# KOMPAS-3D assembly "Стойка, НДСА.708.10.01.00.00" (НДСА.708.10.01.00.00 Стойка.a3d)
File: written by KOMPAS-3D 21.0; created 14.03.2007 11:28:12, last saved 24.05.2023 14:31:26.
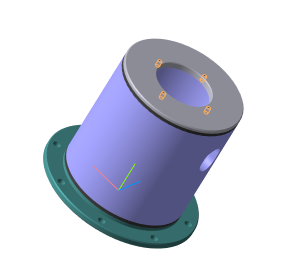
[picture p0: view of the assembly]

Document properties: Полное имя файла: C:\Users\s.pischagina\Desktop\PLM\НДСА.708.10.01.00.00 Стойка.a3d; Автор: Ширяева О.А.; Организация: Эсто-вакуум

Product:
- Part/product: Стойка  | designation НДСА.708.10.01.00.00
    Масса: 10.550806
    additional columns: <item xmlns="http://appius.ru/pdm" xmlns:xs="http://www.w3.org/2001/XMLSchema" x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; <item xmlns="http://appius.ru/pdm" xmlns:xs="http://www.w3.org/2001/XMLSchema" x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; <item xmlns="http://appius.ru/pdm" xmlns:xs="http://www.w3.org/2001/XMLSchema" x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
  - Component [detail]: Шов сварной 1 (стойка)  | qty 2  | Материал: Сталь 20  ГОСТ 1050-88 (density 7820 kg/m3); Масса: 0.054253; additional columns: <item xmlns="http://appius.ru/pdm" xmlns:xs="http://www.w3.org/2001/XMLSchema" x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; <item xmlns="http://appius.ru/pdm" xmlns:xs="http://www.w3.org/2001/XMLSchema" x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; source file: Шов сварной 1 (стойка).m3d
  - Component [detail]: Фланец верхний  | designation НДСА.014.01.09.01.03  | pos. 3  | Материал: Сталь 20  ГОСТ 1050-88 (density 7820 kg/m3); Масса: 1.270585; Форматы листов документа: A4; additional columns: <item xmlns="http://appius.ru/pdm" xmlns:xs="http://www.w3.org/2001/XMLSchema" x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; <item xmlns="http://appius.ru/pdm" xmlns:xs="http://www.w3.org/2001/XMLSchema" x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; <item xmlns="http://appius.ru/pdm" xmlns:xs="http://www.w3.org/2001/XMLSchema" x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; <item xmlns="http://appius.ru/pdm" xmlns:xs="http://www.w3.org/2001/XMLSchema" x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; <item xmlns="http://appius.ru/pdm" xmlns:xs="http://www.w3.org/2001/XMLSchema" x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; <item xmlns="http://appius.ru/pdm" xmlns:xs="http://www.w3.org/2001/XMLSchema" x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; source file: НДСА.014.01.09.01.03 Фланец верхний.CDW, НДСА.014.01.09.01.03 Фланец верхний.m3d
  - Component [detail]: Труба  | designation НДСА.708.10.01.00.01  | pos. 1  | Материал: Труба$d180х10 ГОСТ 8732-78;20 ГОСТ 8731-74$ (density 7859 kg/m3); Масса: 7.249004; additional columns: <item xmlns="http://appius.ru/pdm" xmlns:xs="http://www.w3.org/2001/XMLSchema" x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; <item xmlns="http://appius.ru/pdm" xmlns:xs="http://www.w3.org/2001/XMLSchema" x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; <item xmlns="http://appius.ru/pdm" xmlns:xs="http://www.w3.org/2001/XMLSchema" x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; source file: НДСА.708.10.01.00.01 Труба.CDW, НДСА.708.10.01.00.01 Труба.m3d
  - Component [detail]: Фланец нижний  | designation НДСА.014.01.09.01.01  | pos. 2  | Материал: Сталь 20 ГОСТ 1050-88 (density 7859 kg/m3); Масса: 1.922711; Форматы листов документа: A4; additional columns: <item xmlns="http://appius.ru/pdm" xmlns:xs="http://www.w3.org/2001/XMLSchema" x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; <item xmlns="http://appius.ru/pdm" xmlns:xs="http://www.w3.org/2001/XMLSchema" x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; <item xmlns="http://appius.ru/pdm" xmlns:xs="http://www.w3.org/2001/XMLSchema" x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; <item xmlns="http://appius.ru/pdm" xmlns:xs="http://www.w3.org/2001/XMLSchema" x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; <item xmlns="http://appius.ru/pdm" xmlns:xs="http://www.w3.org/2001/XMLSchema" x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; <item xmlns="http://appius.ru/pdm" xmlns:xs="http://www.w3.org/2001/XMLSchema" x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; source file: НДСА.014.01.09.01.01 Фланец нижний.CDW, НДСА.014.01.09.01.01 Фланец нижний.m3d

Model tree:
1. Плоскость XY
2. Плоскость ZX
3. Плоскость ZY
4. Начало координат
5. Эскиз:1  (labels: Операция выдавливания:1; Операция выдавливания:1; Вырезать элемент выдавливания:1)
6. Вырезать элемент выдавливания:1
     Расстояние 2 = 2
7. Эскиз:2  (labels: Вырезать элемент выдавливания:1)
8. Вырезать элемент выдавливания:2
     Расстояние 2 = 10
9. Эскиз:3  (labels: Операция вращения:1; Операция вращения:1; Операция вращения:1)
10. Вырезать элемент выдавливания:3
     Расстояние 2 = 2
11. Эскиз:5  (labels: Вырезать элемент выдавливания:3)
12. Вырезать элемент выдавливания:5
     Расстояние 2 = 12
13. Эскиз:6  (labels: Вырезать элемент выдавливания:3)
14. Вырезать элемент выдавливания:6
     Расстояние 2 = 10
15. Эскиз:8  (labels: Вырезать элемент выдавливания:1)
16. Вырезать элемент вращения:2
     Угол 1 = 360
17. Эскиз:9  (labels: Вырезать элемент вращения:2; Фаска:2)
18. Вырезать элемент выдавливания:7
     Расстояние 1 = 92
19. Фаска:1  (labels: Вырезать элемент выдавливания:5)
     Угол = 45; Длина 1 = 1; Длина 2 = 1
20. Фаска:2  (labels: Вырезать элемент выдавливания:3)
     Угол = 45; Длина 1 = 1.5; Длина 2 = 1.5
21. Условное изображение резьбы:1  (labels: M6; cil0_24705-2004 coarse; Вырезать элемент выдавливания:6; Вырезать элемент выдавливания:6)
     Длина резьбы = 9; Шаг резьбы = 1; Номинальный диаметр резьбы = 6
22. Подгонка:1  (labels: Вырезать элемент выдавливания:6)
23. Условное изображение резьбы:2  (labels: M6; cil0_24705-2004 coarse; Вырезать элемент выдавливания:6; Вырезать элемент выдавливания:6)
     Длина резьбы = 9; Шаг резьбы = 1; Номинальный диаметр резьбы = 6
24. Подгонка:2  (labels: Вырезать элемент выдавливания:6)
25. Условное изображение резьбы:3  (labels: M6; cil0_24705-2004 coarse; Вырезать элемент выдавливания:6; Вырезать элемент выдавливания:6)
     Длина резьбы = 9; Шаг резьбы = 1; Номинальный диаметр резьбы = 6
26. Подгонка:3  (labels: Вырезать элемент выдавливания:6)
27. Условное изображение резьбы:4  (labels: M6; cil0_24705-2004 coarse; Вырезать элемент выдавливания:6; Вырезать элемент выдавливания:6)
     Длина резьбы = 9; Шаг резьбы = 1; Номинальный диаметр резьбы = 6
28. Подгонка:4  (labels: Вырезать элемент выдавливания:6; Вырезать элемент выдавливания:1; Операция выдавливания:1; Операция выдавливания:1)

Referenced files in C:\Users\s.pischagina\Desktop\PLM\: НДСА.708.10.01.00.01 Труба.m3d, НДСА.708.10.01.00.01 Труба.CDW, НДСА.014.01.09.01.01 Фланец нижний.m3d, НДСА.014.01.09.01.01 Фланец нижний.CDW, НДСА.014.01.09.01.03 Фланец верхний.m3d, НДСА.014.01.09.01.03 Фланец верхний.CDW, Шов сварной 1 (стойка).m3d
Referenced files in E:\НДСА.014.01.09.00.00 Верхняя стойка гидроподъемника\: Шов сварной 1 (стойка).m3d
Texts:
  НДСА.708.10.01.00.01
  НДСА.014.01.09.01.01
  НДСА.014.01.09.01.03
  НДСА.708.10.01.00.00
  НДСА.014.01.09.01.01 Фланец нижний
  НДСА.708.10.01.00.01 Труба
  Шов сварной 1 (стойка) (1)
  НДСА.014.01.09.01.03 Фланец верхний
  Шов сварной 1 (стойка) (2)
